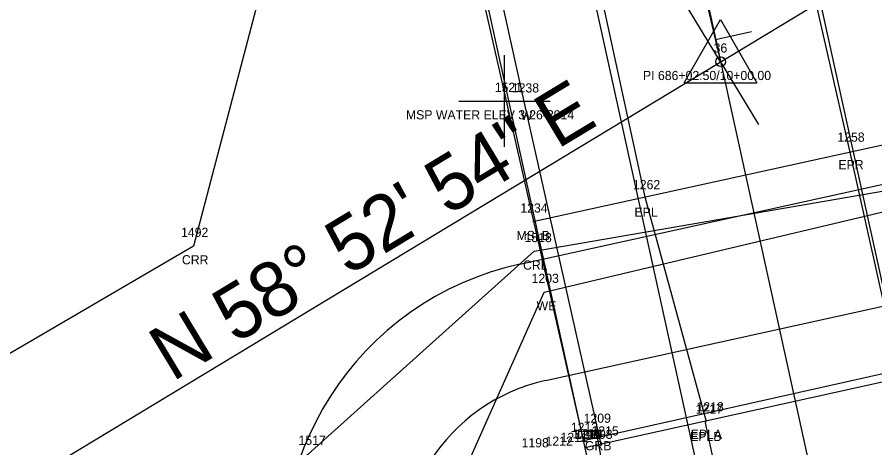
# Model space of a CAD drawing. Extents: x 2521558 to 2549345, y 854846 to 887632.
# Drawn here: x 2523713 to 2523806.5, y 885077.6 to 885124.5 of the extents above; entities that cross this region are included whole.
import ezdxf

# ---------------------------------------------------------------- set-up
doc = ezdxf.new("R2010")
doc.units = 0
for name, color, linetype in [('RD_EX_BldgApp', 7, 'Continuous'), ('RD_EX_BldgApp_txCode', 7, 'Continuous'), ('RD_EX_Bridge', 7, 'Continuous'), ('RD_EX_Bridge_txCode', 7, 'Continuous'), ('RD_EX_Conc_txCode', 7, 'Continuous'), ('RD_EX_GuardRail', 7, 'Continuous'), ('RD_EX_GuardRail_txCode', 7, 'Continuous'), ('RD_EX_H2O', 7, 'Continuous'), ('RD_EX_H2O_txCode', 7, 'Continuous'), ('RD_EX_Misc', 7, 'Continuous'), ('RD_EX_Misc_txCode', 7, 'Continuous'), ('RD_EX_Road', 7, 'Continuous'), ('RD_EX_Road_txCode', 7, 'Continuous'), ('RD_EX_VEG_txCode', 7, 'Continuous'), ('RD_HC_Cl', 7, 'Continuous'), ('RD_HC_Data', 7, 'Continuous'), ('RD_HC_Data_Tic', 7, 'Continuous'), ('RD_HC_txCode', 7, 'Continuous'), ('RD_PD_Bridge', 7, 'Continuous'), ('RD_PD_CstnLmt', 7, 'Continuous'), ('RD_PD_DR_ErosCtrl', 7, 'Continuous'), ('RD_PD_Final_TrvlWay', 7, 'Continuous'), ('RD_PD_RW', 7, 'Continuous'), ('RD_SMD_Locator', 7, 'Continuous')]:
    doc.layers.add(name, color=color, linetype=linetype)

msp = doc.modelspace()

# ---------------------------------------------------------------- linework, layer by layer
at = {"layer": 'RD_EX_BldgApp'}
msp.add_lwpolyline([(2523776.677, 885077.915), (2523768.273, 885115.309), (2523760.204, 885151.895)], dxfattribs=at)
at = {"layer": 'RD_EX_Bridge'}
msp.add_lwpolyline([(2523774.906, 885077.596), (2523821.197, 885087.829), (2523805.064, 885161.895), (2523758.145, 885151.437), (2523774.906, 885077.596)], dxfattribs=at)
at = {"layer": 'RD_EX_GuardRail'}
msp.add_lwpolyline([(2523787.377, 885001.584), (2523782.908, 885042.685), (2523776.151, 885079.302)], dxfattribs=at)
at = {"layer": 'RD_EX_H2O'}
for points in [[(2523582.816, 884766.342), (2523598.112, 884856.984), (2523627.586, 884901.753), (2523623.762, 884928.278), (2523586.58, 884955.428), (2523600.942, 884974.118), (2523633.055, 884997.681), (2523679.166, 885037.048), (2523744.717, 885076.895), (2523769.376, 885098.995), (2523825.47, 885108.66), (2523825.47, 885108.66), (2523845.237, 885110.828), (2523890.252, 885154.934), (2523858.435, 885178.041), (2523850.814, 885196.928), (2523892.509, 885249.744), (2523936.89, 885290.086), (2523980.857, 885285.467), (2524009.058, 885269.77), (2524037.386, 885280.087)], [(2523741.751, 885135.924), (2523732.183, 885099.571), (2523664.897, 885060.261), (2523614.863, 885022.018), (2523558.95, 884972.63), (2523560.622, 884942.416), (2523490.005, 884911.763)], [(2523792.732, 884941.121), (2523763.674, 885051.555), (2523756.264, 885062.719), (2523770.471, 885094.548), (2523817.567, 885105.706), (2523827.825, 885105.996)]]:
    msp.add_lwpolyline(points, dxfattribs=at)
at = {"layer": 'RD_EX_Misc'}
for p, q in [((2523766.128, 885110.375), (2523766.128, 885120.375)), ((2523761.128, 885115.375), (2523771.128, 885115.375)), ((2523816.084, 885112.468), (2523769.205, 885102.217)), ((2523774.429, 885078.307), (2523821.346, 885088.784))]:
    msp.add_line(p, q, dxfattribs=at)
at = {"layer": 'RD_EX_Road'}
for p, q in [((2523803.791, 885109.941), (2523798.302, 885134.145)), ((2523781.516, 885104.768), (2523776.178, 885129.21)), ((2523809.315, 885085.19), (2523803.791, 885109.941)), ((2523788.138, 885080.544), (2523781.516, 885104.768)), ((2523788.047, 885080.306), (2523788.138, 885080.544)), ((2523795.465, 885045.906), (2523788.047, 885080.306))]:
    msp.add_line(p, q, dxfattribs=at)
at = {"layer": 'RD_HC_Cl'}
for p, q in [((2523641.165, 885794.201), (2524197.759, 883266.557)), ((2523672.044, 885048.634), (2523837.18, 885148.323))]:
    msp.add_line(p, q, dxfattribs=at)
at = {"layer": 'RD_HC_Data'}
for p, q in [((2523785.73, 885117.368), (2523789.702, 885124.248)), ((2523789.702, 885124.248), (2523793.671, 885117.368)), ((2523785.73, 885117.368), (2523793.671, 885117.368))]:
    msp.add_line(p, q, dxfattribs=at)
msp.add_circle((2523789.701, 885119.661), 0.529, dxfattribs=at)
at = {"layer": 'RD_HC_Data_Tic'}
for p, q in [((2523789.692, 885119.656), (2523785.558, 885126.504)), ((2523789.164, 885122.1), (2523793.07, 885122.96)), ((2523789.692, 885119.656), (2523793.827, 885112.807))]:
    msp.add_line(p, q, dxfattribs=at)
at = {"layer": 'RD_PD_Bridge'}
msp.add_lwpolyline([(2523752.772, 885178.086), (2523780.729, 885051.128)], dxfattribs=at)
at = {"layer": 'RD_PD_CstnLmt'}
msp.add_lwpolyline([(2523770.593, 885084.896), (2523821.135, 885096.025)], dxfattribs=at)
msp.add_arc((2523774.894, 885065.364), 20, 102.41848, 192.06773, dxfattribs=at)
at = {"layer": 'RD_PD_DR_ErosCtrl'}
msp.add_lwpolyline([(2523767.797, 885097.592), (2523818.34, 885108.721)], dxfattribs=at)
msp.add_arc((2523774.894, 885065.364), 33, 102.41848, 192.06773, dxfattribs=at)
at = {"layer": 'RD_PD_Final_TrvlWay'}
for p, q in [((2523741.744, 885393.246), (2524015.933, 884148.078)), ((2523718.306, 885388.085), (2523992.495, 884142.916))]:
    msp.add_line(p, q, dxfattribs=at)
at = {"layer": 'RD_PD_RW'}
msp.add_line((2523789.736, 885119.635), (2523786.8, 885132.299), dxfattribs=at)
at = {"layer": 'RD_SMD_Locator'}
for centre in [(2523789.701, 885119.661), (2523768.273, 885115.309), (2523803.791, 885109.941), (2523781.516, 885104.768), (2523769.205, 885102.217), (2523732.183, 885099.571), (2523769.376, 885098.995), (2523770.471, 885094.548), (2523788.138, 885080.544), (2523788.047, 885080.306), (2523776.151, 885079.302), (2523774.429, 885078.307), (2523776.677, 885077.915), (2523774.906, 885077.596), (2523774.906, 885077.596)]:
    msp.add_circle(centre, 0.001, dxfattribs=at)

# ---------------------------------------------------------------- texts
at = {"layer": 'RD_EX_BldgApp_txCode'}
for s, p in [('1238', (2523766.926, 885116.309)), ('W', (2523767.903, 885113.309)), ('1215', (2523775.614, 885078.915))]:
    msp.add_text(s, height=1, dxfattribs=at).set_placement(p)
at = {"layer": 'RD_EX_Bridge_txCode'}
for s, p in [('1246', (2523773.536, 885078.596)), ('1210', (2523773.795, 885078.54)), ('1214', (2523773.843, 885078.596)), ('1212', (2523770.605, 885077.8)), ('1211', (2523772.238, 885078.212))]:
    msp.add_text(s, height=1, dxfattribs=at).set_placement(p)
at = {"layer": 'RD_EX_Conc_txCode'}
msp.add_text('1208', height=1, dxfattribs=at).set_placement((2523774.937, 885078.543))
at = {"layer": 'RD_EX_GuardRail_txCode'}
for s, p in [('1209', (2523774.765, 885080.302)), ('GRB', (2523774.899, 885077.302))]:
    msp.add_text(s, height=1, dxfattribs=at).set_placement(p)
at = {"layer": 'RD_EX_H2O_txCode'}
for s, p in [('1492', (2523730.836, 885100.571)), ('1518', (2523768.313, 885099.995)), ('CRR', (2523730.931, 885097.571)), ('CRL', (2523768.148, 885096.995)), ('1203', (2523769.085, 885095.548)), ('WE', (2523769.632, 885092.548)), ('1517', (2523743.655, 885077.895))]:
    msp.add_text(s, height=1, dxfattribs=at).set_placement(p)
at = {"layer": 'RD_EX_Misc_txCode'}
for s, p in [('1521', (2523765.065, 885116.375)), ('MSP WATER ELEV 3-26-2014', (2523755.372, 885113.375)), ('1234', (2523767.858, 885103.217)), ('MSLB', (2523767.441, 885100.217)), ('1213', (2523773.366, 885079.307))]:
    msp.add_text(s, height=1, dxfattribs=at).set_placement(p)
at = {"layer": 'RD_EX_Road_txCode'}
for s, p in [('1258', (2523802.445, 885110.941)), ('EPR', (2523802.563, 885107.941)), ('1262', (2523780.146, 885105.768)), ('EPL', (2523780.311, 885102.768)), ('1217', (2523786.984, 885081.306)), ('1218', (2523787.075, 885081.544)), ('EPLA', (2523786.445, 885078.544)), ('EPLB', (2523786.37, 885078.306))]:
    msp.add_text(s, height=1, dxfattribs=at).set_placement(p)
at = {"layer": 'RD_EX_VEG_txCode'}
msp.add_text('1198', height=1, dxfattribs=at).set_placement((2523767.993, 885077.621))
at = {"layer": 'RD_HC_Data'}
msp.add_text('N 58%%d 52\' 54" E', height=6, rotation=31.1184, dxfattribs=at).set_placement((2523729.873, 885084.712))
at = {"layer": 'RD_HC_txCode'}
for s, p in [('36', (2523788.945, 885120.661)), ('PI 686+02.50/10+00.00', (2523781.236, 885117.661))]:
    msp.add_text(s, height=1, dxfattribs=at).set_placement(p)

doc.saveas('drawing.dxf')
